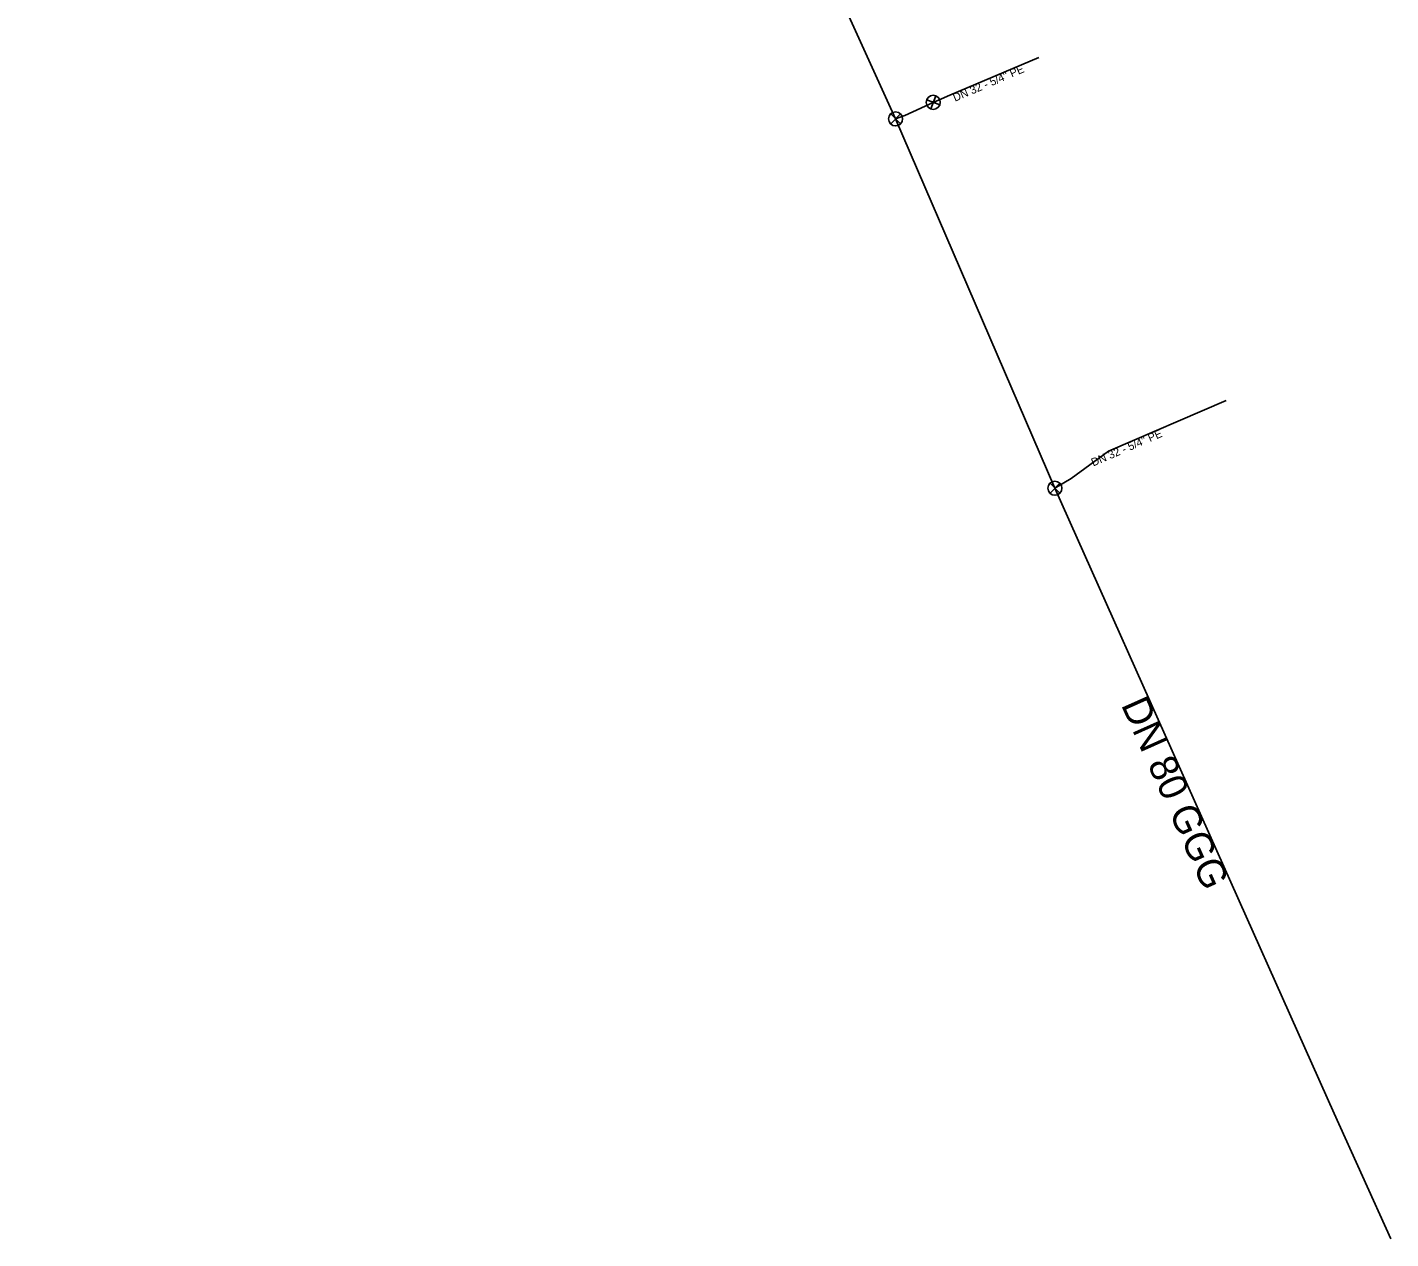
# Model space of a CAD drawing. Extents: x -492321 to -492053, y -1126159 to -1125902.
# Drawn here: x -492248.3 to -492170.8, y -1126159.4 to -1126090.5 of the extents above; entities that cross this region are included whole.
import ezdxf

# ---------------------------------------------------------------- set-up
doc = ezdxf.new("R2010")
doc.units = 0
for name, color, linetype in [('_pripojka_prevzato_z_dokumentace_', 7, 'Continuous'), ('_voda_smvak_prevzato_z_dokumentace_', 7, 'Continuous'), ('Default', 7, 'Continuous'), ('MoLevel 46', 7, 'Continuous'), ('MoLevel 53', 7, 'Continuous'), ('MoLevel 55', 7, 'Continuous')]:
    doc.layers.add(name, color=color, linetype=linetype)

# ---------------------------------------------------------------- blocks, each defined once
blk = doc.blocks.new('_uzaver_pripojka_')
at = {"layer": 'Default'}
for p, q in [((-0.000035, -0.000035), (0.000035, 0.000035)), ((0.000035, -0.000035), (-0.000035, 0.000035))]:
    blk.add_line(p, q, dxfattribs=at)
for radius in [0.00005, 0.0000025]:
    blk.add_circle((0, 0), radius, dxfattribs=at)

msp = doc.modelspace()

# ---------------------------------------------------------------- linework, layer by layer
at = {"layer": '_pripojka_prevzato_z_dokumentace_'}
for p, q in [((-492190.8, -1126092.24), (-492195.86, -1126094.399)), ((-492198.94, -1126095.74), (-492198.41, -1126095.55)), ((-492180.134, -1126111.756), (-492186.835, -1126114.647)), ((-492186.835, -1126114.647), (-492188.95, -1126116.2)), ((-492189.88, -1126116.75), (-492188.95, -1126116.2))]:
    msp.add_line(p, q, dxfattribs=at)
msp.add_lwpolyline([(-492195.86, -1126094.399), (-492196.8, -1126094.8), (-492198.41, -1126095.55)], dxfattribs=at)
at = {"layer": '_voda_smvak_prevzato_z_dokumentace_'}
msp.add_lwpolyline([(-492320.55, -1126109.337), (-492314.27, -1126105.27), (-492304.68, -1126098.93), (-492293.08, -1126091.26), (-492282.11, -1126084.21), (-492270.76, -1126077.22), (-492264.09, -1126073.17), (-492253.41, -1126066.5), (-492241.96, -1126059.49), (-492233.97, -1126054.69), (-492222.62, -1126048.03), (-492221.11, -1126047.14), (-492220.43, -1126048.46), (-492198.94, -1126095.74), (-492189.88, -1126116.75), (-492173.99, -1126152.32), (-492170.782, -1126159.439)], dxfattribs=at)

# ---------------------------------------------------------------- block references
at = {"layer": 'MoLevel 53', "xscale": 8000, "yscale": 7999.999999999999, "rotation": 23.336972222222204}
msp.add_blockref('_uzaver_pripojka_', (-492196.8, -1126094.8), dxfattribs=at)
at = {"layer": 'MoLevel 53', "xscale": 7999.999999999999, "yscale": 7999.999999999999}
for p in [(-492198.94, -1126095.74), (-492189.88, -1126116.75)]:
    msp.add_blockref('_uzaver_pripojka_', p, dxfattribs=at)

# ---------------------------------------------------------------- texts
at = {"layer": 'MoLevel 46'}
msp.add_text('DN 80 GGG', height=1.6049, rotation=294.0715, dxfattribs=at).set_placement((-492186.138, -1126129.061))
at = {"layer": 'MoLevel 55'}
for rotation, p in [(23.10633, (-492195.562, -1126094.766)), (23.33875, (-492187.7, -1126115.516))]:
    msp.add_text("DN 32 - 5/4'' PE", height=0.455, rotation=rotation, dxfattribs=at).set_placement(p)

doc.saveas('drawing.dxf')
